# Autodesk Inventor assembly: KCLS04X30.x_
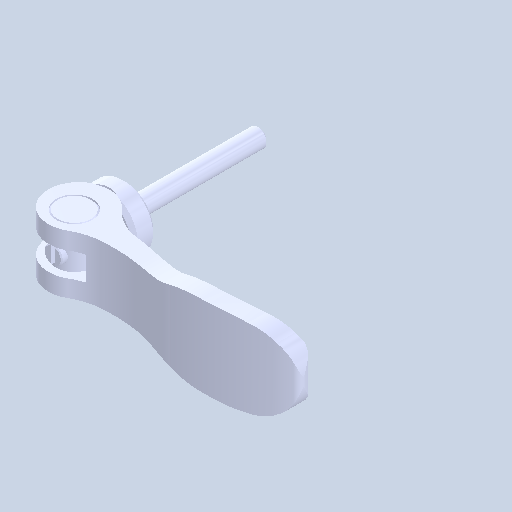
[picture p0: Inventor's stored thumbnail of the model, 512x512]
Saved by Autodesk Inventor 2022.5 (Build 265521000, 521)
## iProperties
Created: 2024-08
Part Number: KCLS04X30.x_
Document SubType Name: Assembly
Designer: ImaoCorp
Author: ImaoCorp
Sending System: SOLIDWORKS 2022-2022290
MC: AMD64
MC_MODEL: Intel64 Family 6 Model 60 Stepping 3, GenuineIntel
OS: Windows_NT
FRU: Parasolid Version 33.1, build 260,  4-25-2022
FORMAT: text
GUISE: transmit
KEY: FILEKCLS04X30.x_t
DATE: Thu Aug 29 10:54:19 2024
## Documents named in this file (5)
- Y:\5.更新分\2024年対応\1001_KCL\データ\kcls04x30\KCLS04X30.x_.iam
- Y:\5.更新分\2024年対応\1001_KCL\データ\kcls04x30\KCLS4X30_01.ipt
- Y:\5.更新分\2024年対応\1001_KCL\データ\kcls04x30\KCLS4X30_02.ipt
- Y:\5.更新分\2024年対応\1001_KCL\データ\kcls04x30\KCLS4X30_03.ipt
- Y:\5.更新分\2024年対応\1001_KCL\データ\kcls04x30\KCLS4X30_04.ipt
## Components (4 placed, 4 different names)
1. KCLS4X30_01
2. KCLS4X30_02
3. KCLS4X30_03
4. KCLS4X30_04
